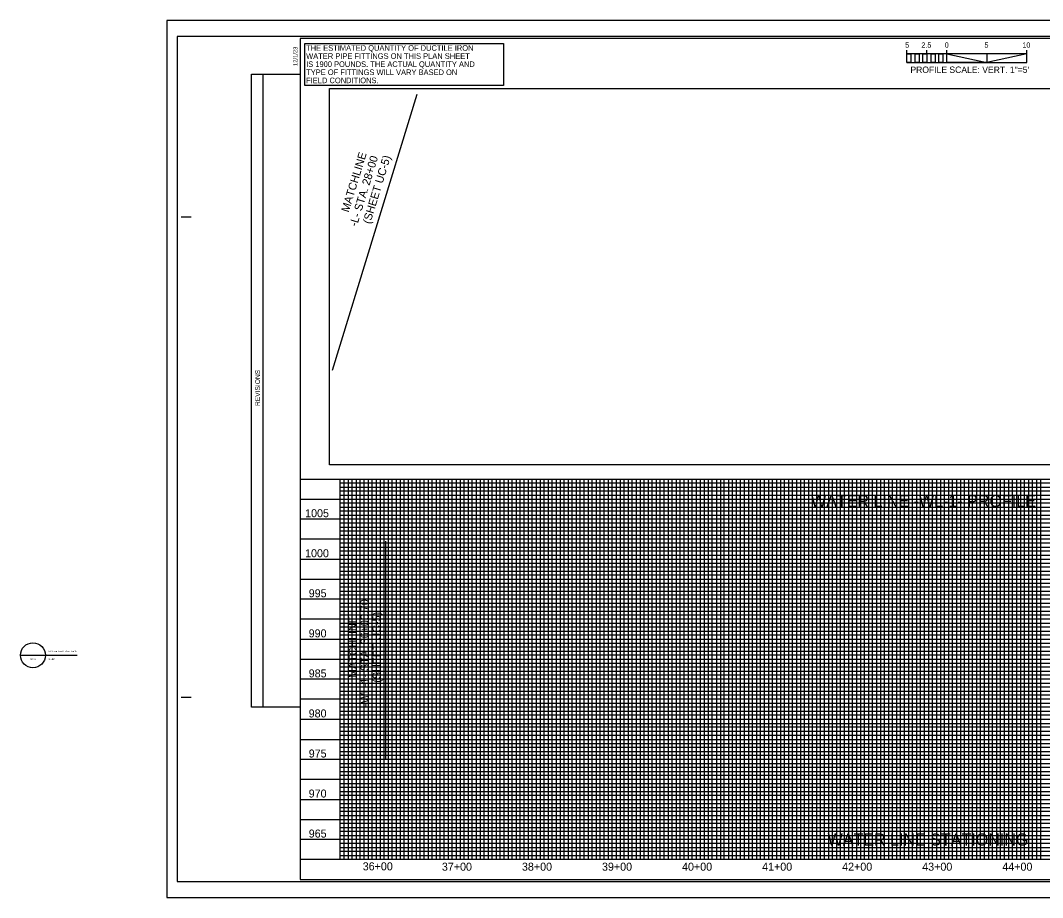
# Model space of a CAD drawing. Extents: x 0 to 7954, y -383 to 1504.
# Drawn here: x -0.277 to 1.851, y 0.008 to 1.833 of the extents above; entities that cross this region are included whole.
import ezdxf

# ---------------------------------------------------------------- set-up
doc = ezdxf.new("R2010")
doc.units = 0
for name, color, linetype in [('Scratch_Level_3', 7, 'Continuous'), ('Sheet Profile Grid Major CELL', 7, 'Continuous'), ('Sheet Profile Grid Middle', 7, 'Continuous'), ('Sheet Profile Grid Minor CELL', 7, 'Continuous'), ('Sheet_Named_Boundary', 7, 'Continuous'), ('UC Plan Profile Sheet 34 CELL', 7, 'Continuous'), ('UC Title Plan Sheet 34 CELL', 7, 'Continuous'), ('Water Line Text and Text Box and Leader Line (B1)', 7, 'Continuous'), ('Water Line Text and Text Box and Leader Line (St)', 7, 'Continuous')]:
    doc.layers.add(name, color=color, linetype=linetype)

msp = doc.modelspace()

# ---------------------------------------------------------------- linework, layer by layer
at = {"layer": 'Scratch_Level_3'}
msp.add_lwpolyline([(0.3664, 0.9085), (0.3664, 1.6915), (2.4667, 1.6915), (2.4667, 1.4997), (2.7575, 1.4997), (2.7575, 0.9085)], close=True, dxfattribs=at)
at = {"layer": 'Sheet Profile Grid Major CELL'}
for points in [[(0.305, 0.8792), (2.5967, 0.8792)], [(0.305, 0.8792), (0.305, 0.0875)], [(0.3883, 0.0875), (0.3883, 0.8792), (0.4717, 0.8792), (0.4717, 0.0875)], [(0.555, 0.0875), (0.555, 0.8792), (0.6383, 0.8792), (0.6383, 0.0875)], [(0.7217, 0.0875), (0.7217, 0.8792), (0.805, 0.8792), (0.805, 0.0875)], [(0.8883, 0.0875), (0.8883, 0.8792), (0.9717, 0.8792), (0.9717, 0.0875)], [(1.055, 0.0875), (1.055, 0.8792), (1.1383, 0.8792), (1.1383, 0.0875)], [(1.2217, 0.0875), (1.2217, 0.8792), (1.305, 0.8792), (1.305, 0.0875)], [(1.3883, 0.0875), (1.3883, 0.8792), (1.4717, 0.8792), (1.4717, 0.0875)], [(1.555, 0.0875), (1.555, 0.8792), (1.6383, 0.8792), (1.6383, 0.0875)], [(1.7217, 0.0875), (1.7217, 0.8792), (1.805, 0.8792), (1.805, 0.0875)], [(2.805, 0.7958), (0.305, 0.7958), (0.305, 0.7125), (2.805, 0.7125)], [(2.805, 0.6292), (0.305, 0.6292), (0.305, 0.5458), (2.805, 0.5458)], [(2.805, 0.4625), (0.305, 0.4625), (0.305, 0.3792), (2.805, 0.3792)], [(2.805, 0.2958), (0.305, 0.2958), (0.305, 0.2125), (2.805, 0.2125)], [(2.805, 0.1292), (0.305, 0.1292)]]:
    msp.add_lwpolyline(points, dxfattribs=at)
at = {"layer": 'Sheet Profile Grid Middle'}
for p, q in [((0.305, 0.8375), (2.5967, 0.8375)), ((2.805, 0.7542), (0.305, 0.7542)), ((0.305, 0.7542), (0.305, 0.6708)), ((0.305, 0.6708), (2.805, 0.6708)), ((2.805, 0.5875), (0.305, 0.5875)), ((0.305, 0.5875), (0.305, 0.5042)), ((0.305, 0.5042), (2.805, 0.5042)), ((2.805, 0.4208), (0.305, 0.4208)), ((0.305, 0.4208), (0.305, 0.3375)), ((0.305, 0.3375), (2.805, 0.3375)), ((2.805, 0.2542), (0.305, 0.2542)), ((0.305, 0.2542), (0.305, 0.1708)), ((0.305, 0.1708), (2.805, 0.1708))]:
    msp.add_line(p, q, dxfattribs=at)
for points in [[(0.43, 0.0875), (0.43, 0.8792), (0.5133, 0.8792), (0.5133, 0.0875)], [(0.5967, 0.0875), (0.5967, 0.8792), (0.68, 0.8792), (0.68, 0.0875)], [(0.7633, 0.0875), (0.7633, 0.8792), (0.8467, 0.8792), (0.8467, 0.0875)], [(0.93, 0.0875), (0.93, 0.8792), (1.0133, 0.8792), (1.0133, 0.0875)], [(1.0967, 0.0875), (1.0967, 0.8792), (1.18, 0.8792), (1.18, 0.0875)], [(1.2633, 0.0875), (1.2633, 0.8792), (1.3467, 0.8792), (1.3467, 0.0875)], [(1.43, 0.0875), (1.43, 0.8792), (1.5133, 0.8792), (1.5133, 0.0875)], [(1.5967, 0.0875), (1.5967, 0.8792), (1.68, 0.8792), (1.68, 0.0875)], [(1.7633, 0.0875), (1.7633, 0.8792), (1.8467, 0.8792), (1.8467, 0.0875)]]:
    msp.add_lwpolyline(points, dxfattribs=at)
at = {"layer": 'Sheet Profile Grid Minor CELL'}
for points in [[(0.3967, 0.0875), (0.3967, 0.8792), (0.405, 0.8792), (0.405, 0.0875)], [(0.4133, 0.0875), (0.4133, 0.8792), (0.4217, 0.8792), (0.4217, 0.0875)], [(0.4383, 0.0875), (0.4383, 0.8792), (0.4467, 0.8792), (0.4467, 0.0875)], [(0.455, 0.0875), (0.455, 0.8792), (0.4633, 0.8792), (0.4633, 0.0875)], [(0.48, 0.0875), (0.48, 0.8792), (0.4883, 0.8792), (0.4883, 0.0875)], [(0.4967, 0.0875), (0.4967, 0.8792), (0.505, 0.8792), (0.505, 0.0875)], [(0.5217, 0.0875), (0.5217, 0.8792), (0.53, 0.8792), (0.53, 0.0875)], [(0.5383, 0.0875), (0.5383, 0.8792), (0.5467, 0.8792), (0.5467, 0.0875)], [(0.5633, 0.0875), (0.5633, 0.8792), (0.5717, 0.8792), (0.5717, 0.0875)], [(0.58, 0.0875), (0.58, 0.8792), (0.5883, 0.8792), (0.5883, 0.0875)], [(0.605, 0.0875), (0.605, 0.8792), (0.6133, 0.8792), (0.6133, 0.0875)], [(0.6217, 0.0875), (0.6217, 0.8792), (0.63, 0.8792), (0.63, 0.0875)], [(0.6467, 0.0875), (0.6467, 0.8792), (0.655, 0.8792), (0.655, 0.0875)], [(0.6633, 0.0875), (0.6633, 0.8792), (0.6717, 0.8792), (0.6717, 0.0875)], [(0.6883, 0.0875), (0.6883, 0.8792), (0.6967, 0.8792), (0.6967, 0.0875)], [(0.705, 0.0875), (0.705, 0.8792), (0.7133, 0.8792), (0.7133, 0.0875)], [(0.73, 0.0875), (0.73, 0.8792), (0.7383, 0.8792), (0.7383, 0.0875)], [(0.7467, 0.0875), (0.7467, 0.8792), (0.755, 0.8792), (0.755, 0.0875)], [(0.7717, 0.0875), (0.7717, 0.8792), (0.78, 0.8792), (0.78, 0.0875)], [(0.7883, 0.0875), (0.7883, 0.8792), (0.7967, 0.8792), (0.7967, 0.0875)], [(0.8133, 0.0875), (0.8133, 0.8792), (0.8217, 0.8792), (0.8217, 0.0875)], [(0.83, 0.0875), (0.83, 0.8792), (0.8383, 0.8792), (0.8383, 0.0875)], [(0.855, 0.0875), (0.855, 0.8792), (0.8633, 0.8792), (0.8633, 0.0875)], [(0.8717, 0.0875), (0.8717, 0.8792), (0.88, 0.8792), (0.88, 0.0875)], [(0.8967, 0.0875), (0.8967, 0.8792), (0.905, 0.8792), (0.905, 0.0875)], [(0.9133, 0.0875), (0.9133, 0.8792), (0.9217, 0.8792), (0.9217, 0.0875)], [(0.9383, 0.0875), (0.9383, 0.8792), (0.9467, 0.8792), (0.9467, 0.0875)], [(0.955, 0.0875), (0.955, 0.8792), (0.9633, 0.8792), (0.9633, 0.0875)], [(0.98, 0.0875), (0.98, 0.8792), (0.9883, 0.8792), (0.9883, 0.0875)], [(0.9967, 0.0875), (0.9967, 0.8792), (1.005, 0.8792), (1.005, 0.0875)], [(1.0217, 0.0875), (1.0217, 0.8792), (1.03, 0.8792), (1.03, 0.0875)], [(1.0383, 0.0875), (1.0383, 0.8792), (1.0467, 0.8792), (1.0467, 0.0875)], [(1.0633, 0.0875), (1.0633, 0.8792), (1.0717, 0.8792), (1.0717, 0.0875)], [(1.08, 0.0875), (1.08, 0.8792), (1.0883, 0.8792), (1.0883, 0.0875)], [(1.105, 0.0875), (1.105, 0.8792), (1.1133, 0.8792), (1.1133, 0.0875)], [(1.1217, 0.0875), (1.1217, 0.8792), (1.13, 0.8792), (1.13, 0.0875)], [(1.1467, 0.0875), (1.1467, 0.8792), (1.155, 0.8792), (1.155, 0.0875)], [(1.1633, 0.0875), (1.1633, 0.8792), (1.1717, 0.8792), (1.1717, 0.0875)], [(1.1883, 0.0875), (1.1883, 0.8792), (1.1967, 0.8792), (1.1967, 0.0875)], [(1.205, 0.0875), (1.205, 0.8792), (1.2133, 0.8792), (1.2133, 0.0875)], [(1.23, 0.0875), (1.23, 0.8792), (1.2383, 0.8792), (1.2383, 0.0875)], [(1.2467, 0.0875), (1.2467, 0.8792), (1.255, 0.8792), (1.255, 0.0875)], [(1.2717, 0.0875), (1.2717, 0.8792), (1.28, 0.8792), (1.28, 0.0875)], [(1.2883, 0.0875), (1.2883, 0.8792), (1.2967, 0.8792), (1.2967, 0.0875)], [(1.3133, 0.0875), (1.3133, 0.8792), (1.3217, 0.8792), (1.3217, 0.0875)], [(1.33, 0.0875), (1.33, 0.8792), (1.3383, 0.8792), (1.3383, 0.0875)], [(1.355, 0.0875), (1.355, 0.8792), (1.3633, 0.8792), (1.3633, 0.0875)], [(1.3717, 0.0875), (1.3717, 0.8792), (1.38, 0.8792), (1.38, 0.0875)], [(1.3967, 0.0875), (1.3967, 0.8792), (1.405, 0.8792), (1.405, 0.0875)], [(1.4133, 0.0875), (1.4133, 0.8792), (1.4217, 0.8792), (1.4217, 0.0875)], [(1.4383, 0.0875), (1.4383, 0.8792), (1.4467, 0.8792), (1.4467, 0.0875)], [(1.455, 0.0875), (1.455, 0.8792), (1.4633, 0.8792), (1.4633, 0.0875)], [(1.48, 0.0875), (1.48, 0.8792), (1.4883, 0.8792), (1.4883, 0.0875)], [(1.4967, 0.0875), (1.4967, 0.8792), (1.505, 0.8792), (1.505, 0.0875)], [(1.5217, 0.0875), (1.5217, 0.8792), (1.53, 0.8792), (1.53, 0.0875)], [(1.5383, 0.0875), (1.5383, 0.8792), (1.5467, 0.8792), (1.5467, 0.0875)], [(1.5633, 0.0875), (1.5633, 0.8792), (1.5717, 0.8792), (1.5717, 0.0875)], [(1.58, 0.0875), (1.58, 0.8792), (1.5883, 0.8792), (1.5883, 0.0875)], [(1.605, 0.0875), (1.605, 0.8792), (1.6133, 0.8792), (1.6133, 0.0875)], [(1.6217, 0.0875), (1.6217, 0.8792), (1.63, 0.8792), (1.63, 0.0875)], [(1.6467, 0.0875), (1.6467, 0.8792), (1.655, 0.8792), (1.655, 0.0875)], [(1.6633, 0.0875), (1.6633, 0.8792), (1.6717, 0.8792), (1.6717, 0.0875)], [(1.6883, 0.0875), (1.6883, 0.8792), (1.6967, 0.8792), (1.6967, 0.0875)], [(1.705, 0.0875), (1.705, 0.8792), (1.7133, 0.8792), (1.7133, 0.0875)], [(1.73, 0.0875), (1.73, 0.8792), (1.7383, 0.8792), (1.7383, 0.0875)], [(1.7467, 0.0875), (1.7467, 0.8792), (1.755, 0.8792), (1.755, 0.0875)], [(1.7717, 0.0875), (1.7717, 0.8792), (1.78, 0.8792), (1.78, 0.0875)], [(1.7883, 0.0875), (1.7883, 0.8792), (1.7967, 0.8792), (1.7967, 0.0875)], [(1.8133, 0.0875), (1.8133, 0.8792), (1.8217, 0.8792), (1.8217, 0.0875)], [(1.83, 0.0875), (1.83, 0.8792), (1.8383, 0.8792), (1.8383, 0.0875)], [(2.5967, 0.8708), (0.3883, 0.8708)], [(2.5967, 0.8542), (0.3883, 0.8542), (0.3883, 0.8625), (2.5967, 0.8625)], [(2.5967, 0.8292), (0.3883, 0.8292), (0.3883, 0.8375), (0.3883, 0.8458), (2.5967, 0.8458)], [(2.5967, 0.8125), (0.3883, 0.8125), (0.3883, 0.8208), (2.5967, 0.8208)], [(2.7217, 0.7875), (0.3883, 0.7875), (0.3883, 0.7958), (0.3883, 0.8042), (2.5967, 0.8042)], [(2.7217, 0.7708), (0.3883, 0.7708), (0.3883, 0.7792), (2.7217, 0.7792)], [(2.7217, 0.7458), (0.3883, 0.7458), (0.3883, 0.7542), (0.3883, 0.7625), (2.7217, 0.7625)], [(2.7217, 0.7292), (0.3883, 0.7292), (0.3883, 0.7375), (2.7217, 0.7375)], [(0.3883, 0.7042), (0.3883, 0.7125), (0.3883, 0.7208), (2.7217, 0.7208)], [(2.7217, 0.6958), (0.3883, 0.6958), (0.3883, 0.7042), (2.7217, 0.7042)], [(2.7217, 0.6792), (0.3883, 0.6792), (0.3883, 0.6875), (2.7217, 0.6875)], [(2.7217, 0.6542), (0.3883, 0.6542), (0.3883, 0.6625), (2.7217, 0.6625)], [(2.7217, 0.6375), (0.3883, 0.6375), (0.3883, 0.6458), (2.7217, 0.6458)], [(2.7217, 0.6125), (0.3883, 0.6125), (0.3883, 0.6208), (2.7217, 0.6208)], [(2.7217, 0.5958), (0.3883, 0.5958), (0.3883, 0.6042), (2.7217, 0.6042)], [(2.7217, 0.5708), (0.3883, 0.5708), (0.3883, 0.5792), (2.7217, 0.5792)], [(2.7217, 0.5542), (0.3883, 0.5542), (0.3883, 0.5625), (2.7217, 0.5625)], [(2.7217, 0.5292), (0.3883, 0.5292), (0.3883, 0.5375), (2.7217, 0.5375)], [(2.7217, 0.5125), (0.3883, 0.5125), (0.3883, 0.5208), (2.7217, 0.5208)], [(2.7217, 0.4875), (0.3883, 0.4875), (0.3883, 0.4958), (2.7217, 0.4958)], [(2.7217, 0.4708), (0.3883, 0.4708), (0.3883, 0.4792), (2.7217, 0.4792)], [(2.7217, 0.4458), (0.3883, 0.4458), (0.3883, 0.4542), (2.7217, 0.4542)], [(2.7217, 0.4292), (0.3883, 0.4292), (0.3883, 0.4375), (2.7217, 0.4375)], [(2.7217, 0.4042), (0.3883, 0.4042), (0.3883, 0.4125), (2.7217, 0.4125)], [(2.7217, 0.3875), (0.3883, 0.3875), (0.3883, 0.3958), (2.7217, 0.3958)], [(2.7217, 0.3625), (0.3883, 0.3625), (0.3883, 0.3708), (2.7217, 0.3708)], [(2.7217, 0.3458), (0.3883, 0.3458), (0.3883, 0.3542), (2.7217, 0.3542)], [(2.7217, 0.3208), (0.3883, 0.3208), (0.3883, 0.3292), (2.7217, 0.3292)], [(2.7217, 0.3042), (0.3883, 0.3042), (0.3883, 0.3125), (2.7217, 0.3125)], [(2.7217, 0.2792), (0.3883, 0.2792), (0.3883, 0.2875), (2.7217, 0.2875)], [(2.7217, 0.2625), (0.3883, 0.2625), (0.3883, 0.2708), (2.7217, 0.2708)], [(2.7217, 0.2375), (0.3883, 0.2375), (0.3883, 0.2458), (2.7217, 0.2458)], [(2.7217, 0.2208), (0.3883, 0.2208), (0.3883, 0.2292), (2.7217, 0.2292)], [(0.3883, 0.1958), (0.3883, 0.2042), (2.7217, 0.2042)], [(0.3883, 0.0958), (2.7217, 0.0958), (2.7217, 0.1042), (0.3883, 0.1042), (0.3883, 0.1125), (2.7217, 0.1125), (2.7217, 0.1208), (0.3883, 0.1208), (0.3883, 0.1292), (0.3883, 0.1375), (2.7217, 0.1375), (2.7217, 0.1458), (0.3883, 0.1458), (0.3883, 0.1542), (2.7217, 0.1542), (2.7217, 0.1625), (0.3883, 0.1625), (0.3883, 0.1708), (0.3883, 0.1792), (2.7217, 0.1792), (2.7217, 0.1875), (0.3883, 0.1875), (0.3883, 0.1958), (2.7217, 0.1958)]]:
    msp.add_lwpolyline(points, dxfattribs=at)
at = {"layer": 'Sheet_Named_Boundary'}
for p, q in [((-0.2771, 0.5125), (-0.225, 0.5125)), ((-0.2771, 0.5125), (-0.225, 0.5125)), ((-0.2771, 0.5125), (-0.225, 0.5125)), ((-0.2508, 0.5125), (-0.1587, 0.5125)), ((-0.2508, 0.5125), (-0.1587, 0.5125)), ((-0.2508, 0.5125), (-0.1587, 0.5125))]:
    msp.add_line(p, q, dxfattribs=at)
msp.add_circle((-0.2511, 0.5125), 0.026, dxfattribs=at)
msp.add_circle((-0.2511, 0.5125), 0.026, dxfattribs=at)
msp.add_circle((-0.2511, 0.5125), 0.026, dxfattribs=at)
at = {"layer": 'UC Plan Profile Sheet 34 CELL'}
for p, q in [((0.2283, 0.4042), (0.2283, 1.7219)), ((0.5479, 1.6796), (0.3719, 1.1047)), ((0.0575, 1.425), (0.0783, 1.425)), ((0.4831, 0.7498), (0.4831, 0.2958)), ((0.0575, 0.425), (0.0783, 0.425)), ((2.805, 0.0875), (0.305, 0.0875)), ((0.305, 0.0458), (0.305, 0.0458)), ((0.305, 0.0458), (0.305, 0.0458)), ((0.305, 0.0458), (0.305, 0.0458)), ((0.305, 0.0458), (0.305, 0.0458)), ((0.305, 0.0458), (0.305, 0.0458))]:
    msp.add_line(p, q, dxfattribs=at)
for points in [[(0.0275, 0.0083), (2.8333, 0.0083), (2.8333, 1.8333), (0.0275, 1.8333)], [(0.0492, 0.0417), (2.8258, 0.0417), (2.8258, 1.8), (0.0492, 1.8)], [(2.805, 1.7958), (0.305, 1.7958), (0.305, 0.0458), (2.805, 0.0458)], [(0.2041, 0.4042), (0.2041, 1.7219), (0.305, 1.7219), (0.305, 0.4042)], [(0.3883, 0.8792), (2.5967, 0.8792), (2.5967, 0.7958), (2.7217, 0.7958), (2.7217, 0.0875), (0.3883, 0.0875)]]:
    msp.add_lwpolyline(points, close=True, dxfattribs=at)
at = {"layer": 'UC Title Plan Sheet 34 CELL'}
for p, q in [((1.5684, 1.746), (1.5684, 1.7713)), ((1.61, 1.7641), (1.61, 1.7713)), ((1.6517, 1.7641), (1.6517, 1.7713)), ((1.8184, 1.7641), (1.8184, 1.7713)), ((1.8184, 1.764), (1.5684, 1.7641)), ((1.5684, 1.7459), (1.8184, 1.7459)), ((1.627, 1.7641), (1.627, 1.746)), ((1.735, 1.7641), (1.735, 1.746)), ((1.8184, 1.7459), (1.8184, 1.7641))]:
    msp.add_line(p, q, dxfattribs=at)
for points in [[(1.5684, 1.7641), (1.5766, 1.7641), (1.5766, 1.7459), (1.5684, 1.7459)], [(1.5857, 1.7641), (1.5939, 1.7641), (1.5939, 1.7459), (1.5857, 1.7459)], [(1.6018, 1.7641), (1.61, 1.7641), (1.61, 1.746), (1.6018, 1.746)], [(1.6187, 1.7641), (1.627, 1.7641), (1.627, 1.746), (1.6187, 1.746)], [(1.6352, 1.7641), (1.6435, 1.7641), (1.6435, 1.7459), (1.6352, 1.746)], [(1.6517, 1.7641), (1.735, 1.746), (1.6517, 1.7459)], [(1.8184, 1.7641), (1.735, 1.746), (1.8184, 1.7459)]]:
    msp.add_lwpolyline(points, close=True, dxfattribs=at)
at = {"layer": 'Water Line Text and Text Box and Leader Line (St)'}
msp.add_lwpolyline([(0.315, 1.7851), (0.7284, 1.7851), (0.7284, 1.6977), (0.315, 1.6977)], close=True, dxfattribs=at)

# ---------------------------------------------------------------- texts
at = {"layer": 'Sheet_Named_Boundary'}
for s, height, p in [('2', 0.00328, (-0.2522, 0.519)), ('2', 0.00328, (-0.2522, 0.519)), ('2', 0.00328, (-0.2522, 0.519)), ('50 Scale Plan Profile - Profile', 0.003281, (-0.2185, 0.519)), ('50 Scale Plan Profile - Profile', 0.003281, (-0.2185, 0.519)), ('50 Scale Plan Profile - Profile', 0.003281, (-0.2185, 0.519)), ('UC-6', 0.00328, (-0.2561, 0.5026)), ('UC-6', 0.00328, (-0.2561, 0.5026)), ('UC-6', 0.00328, (-0.2561, 0.5026)), ('1"=50\'', 0.00328, (-0.2185, 0.5026)), ('1"=50\'', 0.00328, (-0.2185, 0.5026)), ('1"=50\'', 0.00328, (-0.2185, 0.5026))]:
    msp.add_text(s, height=height, dxfattribs=at).set_placement(p)
at = {"layer": 'UC Plan Profile Sheet 34 CELL'}
for s, height, rotation, p in [('12/1/23', 0.00875, 90, (0.2996, 1.7386)), ('MATCHLINE ', 0.01667, 72.9727, (0.4062, 1.4331)), ('-L- STA. 28+00', 0.016667, 72.9727, (0.4233, 1.4036)), ('(SHEET UC-5)', 0.016667, 72.9727, (0.451, 1.4088)), ('REVISIONS', 0.01, 90, (0.2216, 1.0311)), ('-WL-1- STA. 36+06.70', 0.016667, 90.271, (0.4483, 0.4054)), ('(SHEET UC-5)', 0.016667, 90.271, (0.4731, 0.4554)), ('MATCHLINE ', 0.01667, 90.271, (0.4231, 0.4652))]:
    msp.add_text(s, height=height, rotation=rotation, dxfattribs=at).set_placement(p)
for s, p in [('1005', (0.3156, 0.7997)), ('1000', (0.3155, 0.7164)), ('995', (0.3231, 0.6331)), ('990', (0.323, 0.5497)), ('985', (0.3231, 0.4664)), ('980', (0.323, 0.3831)), ('975', (0.3231, 0.2997)), ('970', (0.323, 0.2164)), ('965', (0.3231, 0.1331)), ('36+00', (0.4355, 0.065)), ('37+00', (0.6003, 0.0642)), ('38+00', (0.767, 0.0642)), ('39+00', (0.9336, 0.0642)), ('40+00', (1.1003, 0.0642)), ('41+00', (1.267, 0.0642)), ('42+00', (1.4336, 0.0642)), ('43+00', (1.6003, 0.0642)), ('44+00', (1.767, 0.0642))]:
    msp.add_text(s, height=0.01667, dxfattribs=at).set_placement(p)
at = {"layer": 'UC Title Plan Sheet 34 CELL'}
for s, height, p in [('5', 0.0109, (1.5649, 1.7767)), ('2.5', 0.01087, (1.5985, 1.7767)), ('0', 0.0109, (1.6472, 1.7767)), ('5', 0.0109, (1.7299, 1.7767)), ('10', 0.01087, (1.8088, 1.7767)), ('PROFILE SCALE: VERT. 1"=5\'', 0.013333, (1.5757, 1.7241))]:
    msp.add_text(s, height=height, rotation=0.0014, dxfattribs=at).set_placement(p)
at = {"layer": 'Water Line Text and Text Box and Leader Line (B1)'}
for s, p in [('WATER LINE -WL-1- PROFILE', (1.3688, 0.821)), ('WATER LINE STATIONING', (1.4034, 0.1166))]:
    msp.add_text(s, height=0.025, dxfattribs=at).set_placement(p)
at = {"layer": 'Water Line Text and Text Box and Leader Line (St)'}
for s, p in [('THE ESTIMATED QUANTITY OF DUCTILE IRON', (0.3177, 1.7702)), ('WATER PIPE FITTINGS ON THIS PLAN SHEET', (0.3177, 1.7534)), ('IS 1900 POUNDS. THE ACTUAL QUANTITY AND', (0.3177, 1.7365)), ('TYPE OF FITTINGS WILL VARY BASED ON', (0.3177, 1.7197)), ('FIELD CONDITIONS.', (0.3177, 1.7028))]:
    msp.add_text(s, height=0.011667, dxfattribs=at).set_placement(p)

doc.saveas('drawing.dxf')
